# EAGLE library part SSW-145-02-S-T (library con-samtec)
THROUGH-HOLE .025" SQ POST SOCKET Source: Samtec SSW.pdf
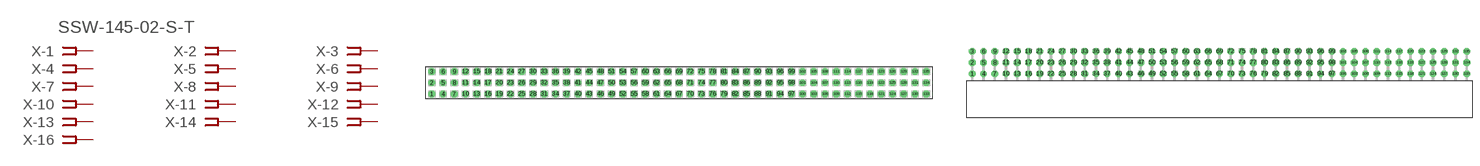
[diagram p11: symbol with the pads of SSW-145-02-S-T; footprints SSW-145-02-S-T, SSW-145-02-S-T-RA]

Designator prefix X; gates -1=FPINV -2=FPIN -3=FPIN -4=FPIN -5=FPIN -6=FPIN -7=FPIN -8=FPIN -9=FPIN -10=FPIN -11=FPIN -12=FPIN -13=FPIN -14=FPIN -15=FPIN -16=FPIN -17=FPIN -18=FPIN -19=FPIN -20=FPIN -21=FPIN -22=FPIN -23=FPIN -24=FPIN -25=FPIN -26=FPIN -27=FPIN -28=FPIN -29=FPIN -30=FPIN -31=FPIN -32=FPIN -33=FPIN -34=FPIN -35=FPIN -36=FPIN -37=FPIN -38=FPIN -39=FPIN -40=FPIN -41=FPIN -42=FPIN -43=FPIN -44=FPIN -45=FPIN -46=FPIN -47=FPIN -48=FPIN -49=FPIN -50=FPIN -51=FPIN -52=FPIN -53=FPIN -54=FPIN -55=FPIN -56=FPIN -57=FPIN -58=FPIN -59=FPIN -60=FPIN -61=FPIN -62=FPIN -63=FPIN -64=FPIN -65=FPIN -66=FPIN -67=FPIN -68=FPIN -69=FPIN -70=FPIN -71=FPIN -72=FPIN -73=FPIN -74=FPIN -75=FPIN -76=FPIN -77=FPIN -78=FPIN -79=FPIN -80=FPIN -81=FPIN -82=FPIN -83=FPIN -84=FPIN -85=FPIN -86=FPIN -87=FPIN -88=FPIN -89=FPIN -90=FPIN -91=FPIN -92=FPIN -93=FPIN -94=FPIN -95=FPIN -96=FPIN -97=FPIN -98=FPIN -99=FPIN -100=FPIN -101=FPIN -102=FPIN -103=FPIN -104=FPIN -105=FPIN -106=FPIN -107=FPIN -108=FPIN -109=FPIN -110=FPIN -111=FPIN -112=FPIN -113=FPIN -114=FPIN -115=FPIN -116=FPIN -117=FPIN -118=FPIN -119=FPIN -120=FPIN -121=FPIN -122=FPIN -123=FPIN -124=FPIN -125=FPIN -126=FPIN -127=FPIN -128=FPIN -129=FPIN -130=FPIN -131=FPIN -132=FPIN -133=FPIN -134=FPIN -135=FPIN

## SSW-145-02-S-T (OC_FARNELL: unknown; OC_NEWARK: unknown)  [SSW-145-02-S-T]
1  -1:1  pas
2  -2:1  pas
3  -3:1  pas
4  -4:1  pas
5  -5:1  pas
6  -6:1  pas
7  -7:1  pas
8  -8:1  pas
9  -9:1  pas
10  -10:1  pas
11  -11:1  pas
12  -12:1  pas
13  -13:1  pas
14  -14:1  pas
15  -15:1  pas
16  -16:1  pas
17  -17:1  pas
18  -18:1  pas
19  -19:1  pas
20  -20:1  pas
21  -21:1  pas
22  -22:1  pas
23  -23:1  pas
24  -24:1  pas
25  -25:1  pas
26  -26:1  pas
27  -27:1  pas
28  -28:1  pas
29  -29:1  pas
30  -30:1  pas
31  -31:1  pas
32  -32:1  pas
33  -33:1  pas
34  -34:1  pas
35  -35:1  pas
36  -36:1  pas
37  -37:1  pas
38  -38:1  pas
39  -39:1  pas
40  -40:1  pas
41  -41:1  pas
42  -42:1  pas
43  -43:1  pas
44  -44:1  pas
45  -45:1  pas
46  -46:1  pas
47  -47:1  pas
48  -48:1  pas
49  -49:1  pas
50  -50:1  pas
51  -51:1  pas
52  -52:1  pas
53  -53:1  pas
54  -54:1  pas
55  -55:1  pas
56  -56:1  pas
57  -57:1  pas
58  -58:1  pas
59  -59:1  pas
60  -60:1  pas
61  -61:1  pas
62  -62:1  pas
63  -63:1  pas
64  -64:1  pas
65  -65:1  pas
66  -66:1  pas
67  -67:1  pas
68  -68:1  pas
69  -69:1  pas
70  -70:1  pas
71  -71:1  pas
72  -72:1  pas
73  -73:1  pas
74  -74:1  pas
75  -75:1  pas
76  -76:1  pas
77  -77:1  pas
78  -78:1  pas
79  -79:1  pas
80  -80:1  pas
81  -81:1  pas
82  -82:1  pas
83  -83:1  pas
84  -84:1  pas
85  -85:1  pas
86  -86:1  pas
87  -87:1  pas
88  -88:1  pas
89  -89:1  pas
90  -90:1  pas
91  -91:1  pas
92  -92:1  pas
93  -93:1  pas
94  -94:1  pas
95  -95:1  pas
96  -96:1  pas
97  -97:1  pas
98  -98:1  pas
99  -99:1  pas
100  -100:1  pas
101  -101:1  pas
102  -102:1  pas
103  -103:1  pas
104  -104:1  pas
105  -105:1  pas
106  -106:1  pas
107  -107:1  pas
108  -108:1  pas
109  -109:1  pas
110  -110:1  pas
111  -111:1  pas
112  -112:1  pas
113  -113:1  pas
114  -114:1  pas
115  -115:1  pas
116  -116:1  pas
117  -117:1  pas
118  -118:1  pas
119  -119:1  pas
120  -120:1  pas
121  -121:1  pas
122  -122:1  pas
123  -123:1  pas
124  -124:1  pas
125  -125:1  pas
126  -126:1  pas
127  -127:1  pas
128  -128:1  pas
129  -129:1  pas
130  -130:1  pas
131  -131:1  pas
132  -132:1  pas
133  -133:1  pas
134  -134:1  pas
135  -135:1  pas

## SSW-145-02-S-TRA (MPN: SSW-145-02-S-T-RA; OC_FARNELL: unknown; OC_NEWARK: 83P1636)  [SSW-145-02-S-T-RA]
Pads as for SSW-145-02-S-T

## Footprint SSW-145-02-S-T (pad centres in mm)
THROUGH-HOLE .025" SQ POST SOCKET Source: Samtec SSW.pdf
drill 1 pad 1.5 octagon: 1 -55.88,-2.54; 2 -55.88,0; 3 -55.88,2.54; 4 -53.34,-2.54; 5 -53.34,0; 6 -53.34,2.54; 7 -50.8,-2.54; 8 -50.8,0; 9 -50.8,2.54; 10 -48.26,-2.54; 11 -48.26,0; 12 -48.26,2.54; 13 -45.72,-2.54; 14 -45.72,0; 15 -45.72,2.54; 16 -43.18,-2.54; 17 -43.18,0; 18 -43.18,2.54; 19 -40.64,-2.54; 20 -40.64,0; 21 -40.64,2.54; 22 -38.1,-2.54; 23 -38.1,0; 24 -38.1,2.54; 25 -35.56,-2.54; 26 -35.56,0; 27 -35.56,2.54; 28 -33.02,-2.54; 29 -33.02,0; 30 -33.02,2.54; 31 -30.48,-2.54; 32 -30.48,0; 33 -30.48,2.54; 34 -27.94,-2.54; 35 -27.94,0; 36 -27.94,2.54; 37 -25.4,-2.54; 38 -25.4,0; 39 -25.4,2.54; 40 -22.86,-2.54; 41 -22.86,0; 42 -22.86,2.54; 43 -20.32,-2.54; 44 -20.32,0; 45 -20.32,2.54; 46 -17.78,-2.54; 47 -17.78,0; 48 -17.78,2.54; 49 -15.24,-2.54; 50 -15.24,0; 51 -15.24,2.54; 52 -12.7,-2.54; 53 -12.7,0; 54 -12.7,2.54; 55 -10.16,-2.54; 56 -10.16,0; 57 -10.16,2.54; 58 -7.62,-2.54; 59 -7.62,0; 60 -7.62,2.54; 61 -5.08,-2.54; 62 -5.08,0; 63 -5.08,2.54; 64 -2.54,-2.54; 65 -2.54,0; 66 -2.54,2.54; 67 0,-2.54; 68 0,0; 69 0,2.54; 70 2.54,-2.54; 71 2.54,0; 72 2.54,2.54; 73 5.08,-2.54; 74 5.08,0; 75 5.08,2.54; 76 7.62,-2.54; 77 7.62,0; 78 7.62,2.54; 79 10.16,-2.54; 80 10.16,0; 81 10.16,2.54; 82 12.7,-2.54; 83 12.7,0; 84 12.7,2.54; 85 15.24,-2.54; 86 15.24,0; 87 15.24,2.54; 88 17.78,-2.54; 89 17.78,0; 90 17.78,2.54; 91 20.32,-2.54; 92 20.32,0; 93 20.32,2.54; 94 22.86,-2.54; 95 22.86,0; 96 22.86,2.54; 97 25.4,-2.54; 98 25.4,0; 99 25.4,2.54; 100 27.94,-2.54; 101 27.94,0; 102 27.94,2.54; 103 30.48,-2.54; 104 30.48,0; 105 30.48,2.54; 106 33.02,-2.54; 107 33.02,0; 108 33.02,2.54; 109 35.56,-2.54; 110 35.56,0; 111 35.56,2.54; 112 38.1,-2.54; 113 38.1,0; 114 38.1,2.54; 115 40.64,-2.54; 116 40.64,0; 117 40.64,2.54; 118 43.18,-2.54; 119 43.18,0; 120 43.18,2.54; 121 45.72,-2.54; 122 45.72,0; 123 45.72,2.54; 124 48.26,-2.54; 125 48.26,0; 126 48.26,2.54; 127 50.8,-2.54; 128 50.8,0; 129 50.8,2.54; 130 53.34,-2.54; 131 53.34,0; 132 53.34,2.54; 133 55.88,-2.54; 134 55.88,0; 135 55.88,2.54

## Footprint SSW-145-02-S-T-RA (pad centres in mm)
THROUGH-HOLE .025" SQ POST SOCKET Source: Samtec SSW.pdf
drill 1 pad 1.5 octagon: 1 -55.88,1.524; 2 -55.88,4.064; 3 -55.88,6.604; 4 -53.34,1.524; 5 -53.34,4.064; 6 -53.34,6.604; 7 -50.8,1.524; 8 -50.8,4.064; 9 -50.8,6.604; 10 -48.26,1.524; 11 -48.26,4.064; 12 -48.26,6.604; 13 -45.72,1.524; 14 -45.72,4.064; 15 -45.72,6.604; 16 -43.18,1.524; 17 -43.18,4.064; 18 -43.18,6.604; 19 -40.64,1.524; 20 -40.64,4.064; 21 -40.64,6.604; 22 -38.1,1.524; 23 -38.1,4.064; 24 -38.1,6.604; 25 -35.56,1.524; 26 -35.56,4.064; 27 -35.56,6.604; 28 -33.02,1.524; 29 -33.02,4.064; 30 -33.02,6.604; 31 -30.48,1.524; 32 -30.48,4.064; 33 -30.48,6.604; 34 -27.94,1.524; 35 -27.94,4.064; 36 -27.94,6.604; 37 -25.4,1.524; 38 -25.4,4.064; 39 -25.4,6.604; 40 -22.86,1.524; 41 -22.86,4.064; 42 -22.86,6.604; 43 -20.32,1.524; 44 -20.32,4.064; 45 -20.32,6.604; 46 -17.78,1.524; 47 -17.78,4.064; 48 -17.78,6.604; 49 -15.24,1.524; 50 -15.24,4.064; 51 -15.24,6.604; 52 -12.7,1.524; 53 -12.7,4.064; 54 -12.7,6.604; 55 -10.16,1.524; 56 -10.16,4.064; 57 -10.16,6.604; 58 -7.62,1.524; 59 -7.62,4.064; 60 -7.62,6.604; 61 -5.08,1.524; 62 -5.08,4.064; 63 -5.08,6.604; 64 -2.54,1.524; 65 -2.54,4.064; 66 -2.54,6.604; 67 0,1.524; 68 0,4.064; 69 0,6.604; 70 2.54,1.524; 71 2.54,4.064; 72 2.54,6.604; 73 5.08,1.524; 74 5.08,4.064; 75 5.08,6.604; 76 7.62,1.524; 77 7.62,4.064; 78 7.62,6.604; 79 10.16,1.524; 80 10.16,4.064; 81 10.16,6.604; 82 12.7,1.524; 83 12.7,4.064; 84 12.7,6.604; 85 15.24,1.524; 86 15.24,4.064; 87 15.24,6.604; 88 17.78,1.524; 89 17.78,4.064; 90 17.78,6.604; 91 20.32,1.524; 92 20.32,4.064; 93 20.32,6.604; 94 22.86,1.524; 95 22.86,4.064; 96 22.86,6.604; 97 25.4,1.524; 98 25.4,4.064; 99 25.4,6.604; 100 27.94,1.524; 101 27.94,4.064; 102 27.94,6.604; 103 30.48,1.524; 104 30.48,4.064; 105 30.48,6.604; 106 33.02,1.524; 107 33.02,4.064; 108 33.02,6.604; 109 35.56,1.524; 110 35.56,4.064; 111 35.56,6.604; 112 38.1,1.524; 113 38.1,4.064; 114 38.1,6.604; 115 40.64,1.524; 116 40.64,4.064; 117 40.64,6.604; 118 43.18,1.524; 119 43.18,4.064; 120 43.18,6.604; 121 45.72,1.524; 122 45.72,4.064; 123 45.72,6.604; 124 48.26,1.524; 125 48.26,4.064; 126 48.26,6.604; 127 50.8,1.524; 128 50.8,4.064; 129 50.8,6.604; 130 53.34,1.524; 131 53.34,4.064; 132 53.34,6.604; 133 55.88,1.524; 134 55.88,4.064; 135 55.88,6.604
